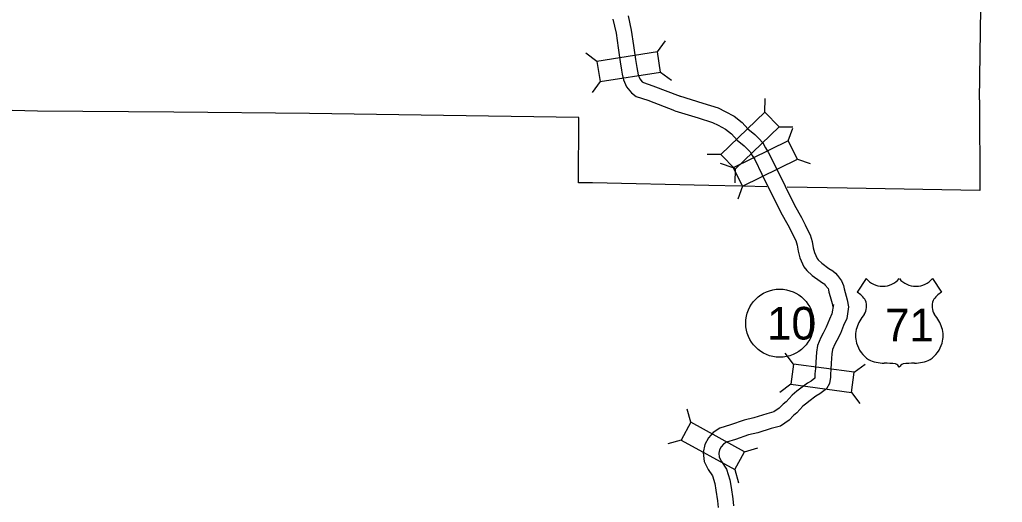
# Model space of a CAD drawing. Extents: x 1382482 to 1385815, y 1168351 to 1170484.
# Drawn here: x 1382910.5 to 1383100.9, y 1170137 to 1170230.6 of the extents above; entities that cross this region are included whole.
import ezdxf

# ---------------------------------------------------------------- set-up
doc = ezdxf.new("R2010")
doc.units = 0
for name, color, linetype in [('15', 7, 'Continuous'), ('20', 7, 'Continuous'), ('22', 7, 'Continuous'), ('8', 7, 'Continuous'), ('Default', 7, 'Continuous')]:
    doc.layers.add(name, color=color, linetype=linetype)

msp = doc.modelspace()

# ---------------------------------------------------------------- linework, layer by layer
at = {"layer": '15'}
for points in [[(1383025.44, 1170230.65), (1383026.05, 1170227.97), (1383026.47, 1170225.11), (1383026.84, 1170222.4), (1383027.09, 1170220.79), (1383027.22, 1170219.98), (1383027.47, 1170218.91), (1383028.06, 1170217.51), (1383029.04, 1170216.34), (1383029.94, 1170215.67), (1383032.18, 1170214.92), (1383037.37, 1170212.94)], [(1383028.37, 1170231.29), (1383029, 1170228.53), (1383029.44, 1170225.53), (1383029.81, 1170222.84), (1383030.06, 1170221.26), (1383030.17, 1170220.56), (1383030.34, 1170219.84), (1383030.65, 1170219.09), (1383031.12, 1170218.53), (1383031.34, 1170218.36), (1383033.19, 1170217.75), (1383038.44, 1170215.74)], [(1383038.35, 1170215.77), (1383042.86, 1170214.37), (1383045.86, 1170213.44), (1383047.2, 1170212.75), (1383048.95, 1170211.84), (1383050.46, 1170210.59), (1383051.58, 1170209.42), (1383052.94, 1170208.3), (1383053.71, 1170207.5), (1383054.48, 1170206.7), (1383055.02, 1170205.71), (1383055.55, 1170204.88), (1383056.98, 1170201.96), (1383060.65, 1170194.57), (1383061.97, 1170192.21), (1383062.7, 1170190.77), (1383063.24, 1170189.7), (1383063.68, 1170188.83), (1383064.05, 1170187.52), (1383064.27, 1170186.29), (1383064.5, 1170185.39), (1383065.02, 1170184.22), (1383065.21, 1170183.99), (1383065.94, 1170183.31), (1383067.31, 1170182.32), (1383068.04, 1170181.85), (1383068.58, 1170181.4), (1383068.95, 1170180.92), (1383069.76, 1170179.93), (1383070.12, 1170178.98), (1383070.24, 1170178.37), (1383070.43, 1170177.65), (1383070.83, 1170176.26), (1383071.12, 1170174.86)], [(1383037.46, 1170212.91), (1383041.97, 1170211.51), (1383044.72, 1170210.65), (1383045.82, 1170210.09), (1383047.28, 1170209.32), (1383048.42, 1170208.39), (1383049.53, 1170207.22), (1383050.9, 1170206.09), (1383051.55, 1170205.42), (1383052.04, 1170204.91), (1383052.43, 1170204.2), (1383052.92, 1170203.42), (1383054.29, 1170200.63), (1383057.99, 1170193.18), (1383059.32, 1170190.79), (1383060.02, 1170189.41), (1383060.57, 1170188.33), (1383060.88, 1170187.74), (1383061.12, 1170186.85), (1383061.33, 1170185.66), (1383061.66, 1170184.4), (1383062.43, 1170182.65), (1383063.01, 1170181.94), (1383064.04, 1170180.98), (1383065.62, 1170179.84), (1383066.27, 1170179.42), (1383066.41, 1170179.31), (1383066.59, 1170179.07), (1383067.13, 1170178.41), (1383067.23, 1170178.14), (1383067.31, 1170177.71), (1383067.53, 1170176.86), (1383067.91, 1170175.54), (1383068.05, 1170174.88)], [(1383068.16, 1170175.33), (1383067.87, 1170173.51), (1383067.39, 1170172.47), (1383066.78, 1170170.96), (1383066.19, 1170169.76), (1383065.75, 1170168.94), (1383065.06, 1170167.39), (1383064.89, 1170166.05), (1383064.74, 1170164.14), (1383064.69, 1170162.92), (1383064.59, 1170161.91), (1383064.6, 1170161.38), (1383064.55, 1170161.03), (1383064.55, 1170161.02), (1383063.85, 1170160.48), (1383063.14, 1170160.07), (1383061.57, 1170158.9), (1383061.11, 1170158.54), (1383060.17, 1170157.74), (1383059.01, 1170156.47), (1383058.43, 1170155.99), (1383057.65, 1170155.21), (1383056.64, 1170154.5), (1383055.29, 1170154.15), (1383052.75, 1170153.34), (1383050.86, 1170152.92), (1383048.24, 1170151.98), (1383046.14, 1170151.36), (1383044.89, 1170150.51), (1383043.95, 1170149.48), (1383043.24, 1170148.19), (1383042.94, 1170146.65), (1383043.09, 1170144.88), (1383043.91, 1170143.34), (1383044.73, 1170142.1), (1383045.16, 1170140.64), (1383045.41, 1170139.33), (1383045.71, 1170137.28), (1383045.83, 1170135.94)], [(1383071.12, 1170174.86), (1383070.76, 1170172.63), (1383070.15, 1170171.28), (1383069.52, 1170169.73), (1383068.85, 1170168.37), (1383068.44, 1170167.62), (1383067.98, 1170166.57), (1383067.87, 1170165.74), (1383067.74, 1170163.97), (1383067.68, 1170162.71), (1383067.59, 1170161.8), (1383067.61, 1170161.21), (1383067.44, 1170160.01), (1383066.83, 1170158.99), (1383065.52, 1170157.98), (1383064.78, 1170157.56), (1383063.41, 1170156.53), (1383063.01, 1170156.21), (1383062.25, 1170155.58), (1383061.08, 1170154.3), (1383060.45, 1170153.77), (1383059.59, 1170152.91), (1383057.92, 1170151.73), (1383056.12, 1170151.27), (1383053.54, 1170150.44), (1383051.7, 1170150.03), (1383049.17, 1170149.13), (1383047.44, 1170148.61), (1383046.86, 1170148.23), (1383046.41, 1170147.73), (1383046.1, 1170147.16), (1383045.97, 1170146.49), (1383046.03, 1170145.74), (1383046.49, 1170144.88), (1383047.48, 1170143.39), (1383048.08, 1170141.35), (1383048.37, 1170139.82), (1383048.69, 1170137.63), (1383048.81, 1170136.29)]]:
    msp.add_lwpolyline(points, dxfattribs=at)
at = {"layer": '20'}
for p, q in [((1383034.07, 1170224.32), (1383035.63, 1170226.45)), ((1383022.33, 1170222.48), (1383020.2, 1170224.04)), ((1383034.68, 1170220.41), (1383036.81, 1170218.85)), ((1383022.94, 1170218.57), (1383021.39, 1170216.44)), ((1383054.91, 1170212.65), (1383054.95, 1170215.29)), ((1383057.66, 1170209.8), (1383060.3, 1170209.76)), ((1383059.43, 1170207.04), (1383060.28, 1170209.54)), ((1383046.37, 1170204.39), (1383043.73, 1170204.43)), ((1383048.77, 1170201.8), (1383046.27, 1170202.65)), ((1383061.18, 1170203.49), (1383063.68, 1170202.64)), ((1383049.13, 1170201.54), (1383049.08, 1170198.9)), ((1383050.52, 1170198.24), (1383049.66, 1170195.75)), ((1383060.45, 1170163.78), (1383058.85, 1170165.89)), ((1383072.22, 1170162.17), (1383074.32, 1170163.77)), ((1383059.91, 1170159.86), (1383057.81, 1170158.26)), ((1383071.68, 1170158.25), (1383073.28, 1170156.15)), ((1383040.55, 1170152.51), (1383039.81, 1170155.04)), ((1383038.64, 1170149.04), (1383036.1, 1170148.3)), ((1383050.96, 1170146.78), (1383053.49, 1170147.51)), ((1383049.05, 1170143.31), (1383049.78, 1170140.77))]:
    msp.add_line(p, q, dxfattribs=at)
for points in [[(1383034.07, 1170224.32), (1383022.33, 1170222.48), (1383022.94, 1170218.57), (1383034.68, 1170220.41)], [(1383049.13, 1170201.54), (1383057.66, 1170209.8), (1383054.91, 1170212.65), (1383046.37, 1170204.39)], [(1383059.43, 1170207.04), (1383048.77, 1170201.8), (1383050.52, 1170198.24), (1383061.18, 1170203.49)], [(1383059.91, 1170159.86), (1383071.68, 1170158.25), (1383072.22, 1170162.17), (1383060.45, 1170163.78)], [(1383050.96, 1170146.78), (1383040.55, 1170152.51), (1383038.64, 1170149.04), (1383049.05, 1170143.31)]]:
    msp.add_lwpolyline(points, close=True, dxfattribs=at)
at = {"layer": '22'}
for p, q in [((1383074.51, 1170180.36), (1383072.78, 1170177.69)), ((1383087.38, 1170180.36), (1383089.11, 1170177.69))]:
    msp.add_line(p, q, dxfattribs=at)
for centre, radius, start, end in [((1383077.73, 1170183.07), 4.21, 220.075, 319.6701), ((1383084.16, 1170183.07), 4.21, 220.3299, 319.925), ((1383070.52, 1170173.8), 4.5, 30.7809, 59.9883), ((1383091.37, 1170173.8), 4.5, 120.0117, 149.2191), ((1383071.51, 1170174.99), 3.08, 328.8105, 21.2108), ((1383090.38, 1170174.99), 3.08, 158.7892, 211.1895), ((1383079.57, 1170168.67), 7.19, 138.9565, 162.6913), ((1383082.32, 1170168.67), 7.19, 17.3087, 41.0435), ((1383077.19, 1170169.26), 4.75, 160.9576, 197.3819), ((1383084.69, 1170169.26), 4.75, 342.6181, 19.0424), ((1383077.97, 1170169.27), 5.5, 195.1074, 237.1312), ((1383083.92, 1170169.27), 5.5, 302.8688, 344.8926), ((1383078.07, 1170171), 7.06, 244.0771, 269.5779), ((1383078.23, 1170151.01), 12.93, 81.1942, 90.9539), ((1383079.85, 1170162.61), 1.24, 28.0342, 72.9864), ((1383082.04, 1170162.61), 1.24, 107.0136, 151.9658), ((1383083.66, 1170151.01), 12.93, 89.0461, 98.8058), ((1383083.82, 1170171), 7.06, 270.4221, 295.9229)]:
    msp.add_arc(centre, radius, start, end, dxfattribs=at)
at = {"layer": '8'}
for points in [[(1383096.49, 1170215.03), (1383096.82, 1170237.25), (1383122.6, 1170236.68), (1383150.22, 1170235.97), (1383176.91, 1170235.2), (1383176.95, 1170235.7), (1383203.59, 1170235.9), (1383203.66, 1170261.85)], [(1383096.49, 1170215.03), (1383096.54, 1170197.46), (1383070.84, 1170197.89), (1383059.19, 1170198.1)], [(1383018.81, 1170211.59), (1382992.62, 1170211.99), (1382966.6, 1170212.38), (1382940.31, 1170212.65), (1382913.91, 1170212.79), (1382894.24, 1170213.35)], [(1383021.45, 1170198.9), (1383018.75, 1170198.94), (1383018.81, 1170211.59)], [(1383050.26, 1170198.26), (1383044.01, 1170198.37), (1383021.45, 1170198.9)], [(1383055.28, 1170198.17), (1383050.65, 1170198.25)]]:
    msp.add_lwpolyline(points, dxfattribs=at)
at = {"layer": 'Default'}
msp.add_circle((1383057.77, 1170171.7), 6.6, dxfattribs=at)

# ---------------------------------------------------------------- texts
at = {"layer": '22'}
msp.add_text('71', height=6.336, dxfattribs=at).set_placement((1383078.19, 1170168.17))
at = {"layer": 'Default'}
msp.add_text('10', height=6.336, dxfattribs=at).set_placement((1383055.33, 1170168.53))

doc.saveas('drawing.dxf')
